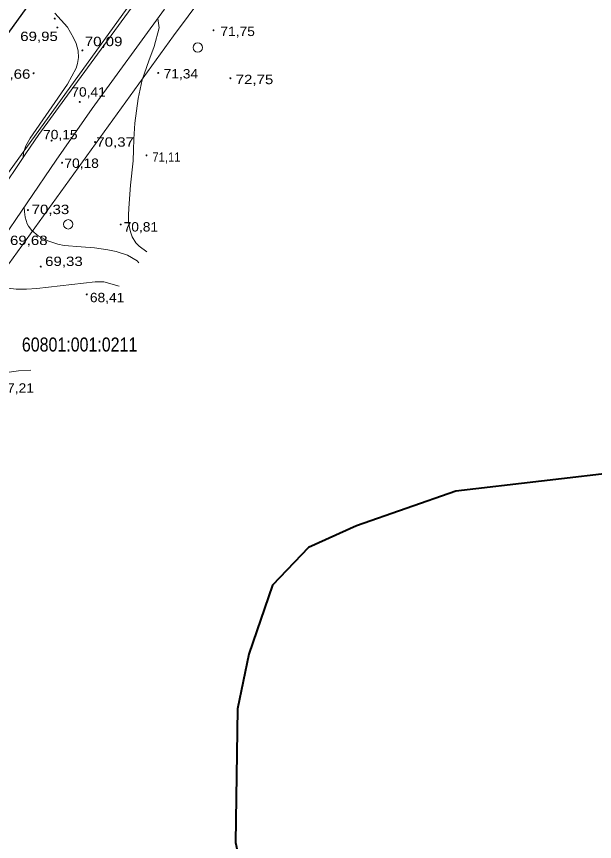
# Model space of a CAD drawing. Extents: x 628176 to 629009, y 6439913 to 6440496.
# Drawn here: x 628602.9 to 628726.4, y 6440112.2 to 6440288.3 of the extents above; entities that cross this region are included whole.
import ezdxf
from ezdxf.enums import TextEntityAlignment as Align

# ---------------------------------------------------------------- set-up
doc = ezdxf.new("R2010")
doc.units = 0
doc.header["$LTSCALE"] = 0.8
for name, color, linetype, lineweight in [('1', 7, 'Continuous', 13), ('11', 7, 'Continuous', 13), ('14', 7, 'Continuous', 25), ('20', 7, 'Continuous', 40), ('3', 7, 'Continuous', 13), ('6', 7, 'Continuous', 13)]:
    doc.layers.add(name, color=color, linetype=linetype, lineweight=lineweight)
doc.layers.add('23', color=7, linetype='Continuous')

msp = doc.modelspace()

# ---------------------------------------------------------------- hatches: boundary and pattern name
at = {"layer": '1'}
for points in [[(628611.1988, 6440287.8256, 1), (628610.9988, 6440287.8256, 1)], [(628611.7711, 6440285.941, 1), (628611.5711, 6440285.941, 1)], [(628645.1155, 6440285.3428, 1), (628644.9155, 6440285.3428, 1)], [(628617.1125, 6440281.0346, 1), (628616.9125, 6440281.0346, 1)], [(628606.6905, 6440276.1625, 1), (628606.4905, 6440276.1625, 1)], [(628633.314, 6440276.2393, 1), (628633.114, 6440276.2393, 1)], [(628648.7156, 6440275.1011, 1), (628648.5156, 6440275.1011, 1)], [(628616.537, 6440270.0342, 1), (628616.337, 6440270.0342, 1)], [(628610.531, 6440261.787, 1), (628610.331, 6440261.787, 1)], [(628619.8127, 6440261.466, 1), (628619.6127, 6440261.466, 1)], [(628630.7974, 6440258.6282, 1), (628630.5974, 6440258.6282, 1)], [(628612.774, 6440257.079, 1), (628612.574, 6440257.079, 1)], [(628605.464, 6440246.9675, 1), (628605.264, 6440246.9675, 1)], [(628625.3078, 6440243.8859, 1), (628625.1078, 6440243.8859, 1)], [(628608.213, 6440234.9014, 1), (628608.013, 6440234.9014, 1)], [(628618.0272, 6440228.9631, 1), (628617.8272, 6440228.9631, 1)]]:
    msp.add_hatch(color=256, dxfattribs=at).paths.add_polyline_path(points)

# ---------------------------------------------------------------- linework, layer by layer
for p, q in [((628613.8, 6440271.46), (628629.23, 6440292.59)), ((628619.08, 6440268.61), (628634.56, 6440289.83)), ((628613.8, 6440271.46), (628607.73, 6440263.09)), ((628619.08, 6440268.61), (628611.39, 6440257.62)), ((628604.9, 6440259.07), (628607.73, 6440263.09)), ((628604.9, 6440259.07), (628588.52, 6440234.65)), ((628611.39, 6440257.62), (628593.63, 6440231.52))]:
    msp.add_line(p, q, dxfattribs=at)
for centre, radius in [((628611.0988, 6440287.8256), 0.1), ((628611.6711, 6440285.941), 0.1), ((628645.0155, 6440285.3428), 0.1), ((628641.6448, 6440281.6633), 1), ((628617.0125, 6440281.0346), 0.1), ((628606.5905, 6440276.1625), 0.1), ((628633.214, 6440276.2393), 0.1), ((628648.6156, 6440275.1011), 0.1), ((628616.437, 6440270.0342), 0.1), ((628610.431, 6440261.787), 0.1), ((628619.7127, 6440261.466), 0.1), ((628630.6974, 6440258.6282), 0.1), ((628612.674, 6440257.079), 0.1), ((628605.364, 6440246.9675), 0.1), ((628613.9826, 6440243.9186), 1), ((628625.2078, 6440243.8859), 0.1), ((628608.113, 6440234.9014), 0.1), ((628617.9272, 6440228.9631), 0.1)]:
    msp.add_circle(centre, radius, dxfattribs=at)
at = {"layer": '11'}
msp.add_lwpolyline([(628709.76, 6440416.52), (628665.41, 6440371.4), (628640.59, 6440339.47), (628612.95, 6440301.12), (628547.63, 6440210.77)], dxfattribs=at)
at = {"layer": '14'}
msp.add_lwpolyline([(628648.46, 6440349.59), (628617.39, 6440307.28), (628547.63, 6440210.77), (628497.5, 6440118.54), (628474.19, 6440080.39)], dxfattribs=at)
at = {"layer": '20'}
for points in [[(628760.23, 6440259.05), (628733.4, 6440191.22), (628696.75, 6440186.92), (628675.56, 6440179.58), (628665.34, 6440174.89), (628657.6, 6440166.85), (628652.57, 6440152.14), (628650.11, 6440140.45)], [(628650.11, 6440140.45), (628649.71, 6440111.91), (628653.77, 6440093.25), (628666.38, 6440069.11), (628676.78, 6440050.71), (628684.75, 6440039.11), (628692.3, 6440028.67)]]:
    msp.add_lwpolyline(points, dxfattribs=at)
at = {"layer": '3'}
for p, q in [((628628.9, 6440270.75), (628628.24, 6440265.51)), ((628628.24, 6440265.51), (628628, 6440262.12)), ((628627.94, 6440259.81), (628628, 6440262.12)), ((628604.34, 6440258.24), (628604.43, 6440259.15)), ((628604.9, 6440260.65), (628604.43, 6440259.15)), ((628627.83, 6440257.5), (628627.94, 6440259.81)), ((628626.84, 6440245.88), (628626.9, 6440247.37)), ((628626.89, 6440244.48), (628626.84, 6440245.88)), ((628626.89, 6440244.48), (628627.06, 6440243.22)), ((628627.25, 6440242.34), (628627.06, 6440243.22)), ((628622.46, 6440238.5), (628619.62, 6440238.87)), ((628622.46, 6440238.5), (628624.24, 6440238.15)), ((628626.66, 6440237.32), (628624.24, 6440238.15)), ((628619.77, 6440231.64), (628607.25, 6440230.24)), ((628621.57, 6440231.64), (628619.77, 6440231.64)), ((628621.57, 6440231.64), (628624.86, 6440230.74)), ((628605.98, 6440212.75), (628603.33, 6440212.62))]:
    msp.add_line(p, q, dxfattribs=at)
for points in [[(628611.1, 6440289), (628613.8, 6440286), (628615.13, 6440283.75)], [(628632.34, 6440281.89), (628633.43, 6440285.86), (628633.13, 6440287.87)], [(628615.13, 6440283.75), (628615.71, 6440282.55), (628616.09, 6440280.97), (628616.16, 6440279.5), (628615.97, 6440278.27), (628615.65, 6440277.29), (628613.8, 6440273.82)], [(628628.9, 6440270.75), (628629.75, 6440274.74), (628631.19, 6440278.83), (628632.34, 6440281.89)], [(628604.9, 6440260.65), (628605.87, 6440262.32), (628613.8, 6440273.82)], [(628627.83, 6440257.5), (628627.26, 6440252.31), (628626.9, 6440247.37)], [(628606.2, 6440242.63), (628605.46, 6440243.53), (628605.24, 6440244.04), (628604.79, 6440245.42), (628604.64, 6440246.55), (628604.54, 6440247.55)], [(628606.2, 6440242.63), (628607.56, 6440241.44), (628609.62, 6440240.38), (628611.78, 6440239.66), (628613.13, 6440239.42), (628616.72, 6440239.1), (628619.62, 6440238.87)], [(628627.25, 6440242.34), (628627.65, 6440241.25), (628628.44, 6440239.97), (628629.17, 6440239.23), (628630.75, 6440238.06)], [(628626.66, 6440237.32), (628628.73, 6440236.09), (628629.09, 6440235.73)], [(628594.13, 6440232.25), (628595.78, 6440231.52), (628599.36, 6440230.53), (628602.88, 6440230.04), (628605.07, 6440230.1), (628607.25, 6440230.24)], [(628587.19, 6440210.42), (628595.65, 6440211.27), (628599.9, 6440212.15), (628603.33, 6440212.62)]]:
    msp.add_lwpolyline(points, dxfattribs=at)
at = {"layer": '6'}
for points in [[(628713.84, 6440420.66), (628737.18, 6440419.44), (628678.6, 6440359.86), (628654.6, 6440328.98), (628627.14, 6440290.88), (628627.14, 6440290.88), (628627.14, 6440290.88), (628562.66, 6440201.7), (628536.24, 6440148.38), (628489.22, 6440071.42), (628480.02, 6440052.78), (628457.03, 6440037.16), (628421.17, 6440028.67)], [(628753.89, 6440420.62), (628687.68, 6440352.8), (628636.46, 6440284.16), (628572.54, 6440195.74), (628546.32, 6440142.82), (628546.32, 6440142.82), (628546.32, 6440142.82), (628498.7, 6440064.9), (628484.24, 6440046.28), (628473.72, 6440036.18), (628464.05, 6440028.67)]]:
    msp.add_lwpolyline(points, dxfattribs=at)

# ---------------------------------------------------------------- texts
at = {"layer": '1'}
for s, width, p in [('71,75', 1.1, (628646.49, 6440284.11)), ('69,95', 1.2, (628603.73, 6440283.05)), ('70,09', 1.2, (628617.53, 6440281.96)), ('69,66', 1.2, (628597.86, 6440275)), ('71,34', 1.1, (628634.36, 6440275.06)), ('72,75', 1.2, (628649.76, 6440273.84)), ('70,41', 1.1, (628614.65, 6440271.18)), ('70,15', 1.1, (628608.61, 6440262.08)), ('70,37', 1.2, (628619.99, 6440260.49)), ('71,11', 0.9, (628631.95, 6440257.26)), ('70,18', 1.1, (628613.16, 6440255.97)), ('70,33', 1.2, (628606.17, 6440246.1)), ('70,81', 1.1, (628625.82, 6440242.38)), ('69,68', 1.2, (628601.54, 6440239.5)), ('69,33', 1.2, (628609.05, 6440235.02)), ('68,41', 1.1, (628618.61, 6440227.29)), ('67,21', 1.1, (628599.29, 6440207.98))]:
    msp.add_text(s, height=2, dxfattribs=dict(at, width=width)).set_placement(p)
at = {"layer": '23', "width": 0.85}
msp.add_text('60801:001:0211', height=3, dxfattribs=at).set_placement((628616.41, 6440216.76), align=Align.CENTER)

doc.saveas('drawing.dxf')
